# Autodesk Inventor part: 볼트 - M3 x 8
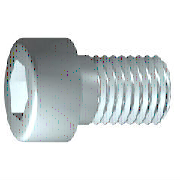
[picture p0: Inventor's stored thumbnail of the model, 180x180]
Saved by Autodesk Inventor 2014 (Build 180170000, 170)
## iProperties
IsCustomPart: 0
Created: 2012-02
Part Number: 볼트 - M3 x 8
Material: 스테인리스강
Description: 6각 소켓 머리 캡 나사
Document SubType Name: Modeling
Standard: ISO 4762
Designer: mduedu
Standard Revision: Fourth edition 2004-03-01
Standards Organization: ISO
Language: ko-KR
Size Designation: M3 x 8
Categories: <MemberInstance><Categories><Category DisplayName="조임쇠" InternalName="e4da775c-781d-43d5-af7c-5136215cf5a6" Mnemonic="FSTN"><Category DisplayName="볼트" InternalN
Density: 8.08 g/cm^3
Appearance: 반광택
Mass: 0.95587 g
Surface Area: 1.83001 cm^2
Volume: 0.118301 cm^3
Author: mduedu
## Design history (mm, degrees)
sketch "스케치1"
  geometry: L1 (-0.867, 0)-(8, 0); L2 (8, 0)-(8, 1.5); L3 (8, 1.5)-(1.25, 1.5); L4 (1.25, 1.5)-(0.943, 1.5); L5 (0.943, 1.5)-(0, 1.5); L6 (0, 1.5)-(0, 2.75); L7 (0, 2.75)-(-3, 2.75); L8 (-3, 2.75)-(-3, 1.443); L9 (-3, 1.443)-(-1.7, 1.443); L10 (-1.7, 1.443)-(-0.867, 0); L11 (-5.2, 0)-(10.2, 0) reference; L12 (0, -0.55)-(0, 3.3) reference; L13 (1.25, 1.5)-(0, 1.5)
  constraints: 22 end point, 6 parallel, 2 collinear, 2 perpendicular, 1 horizontal, 1 point on line
  dimensions: "d1" = 6.75 distance from line of L3.end L2 (= GEL); "d2" = 0.30683 distance of L4.end L3.end (computed from GAL); "d3" = 3 distance between parallel lines of L8 L6 (= KOH); "d4" = 1.3 distance of L8.end L9.end (= INTI); "d5" = 60 deg angle of L10 L1; "d6" = 3 diameter of L3 L1 (= GD); "d7" = 3 diameter of L5 L1 (= BDM); "d8" = 2.88675 diameter of L9 L1 (= 1.1547 x SW); "d9" = 5.5 diameter of L7 L1 (= KOD); "d26" = 8 distance between parallel lines of L12 L2 (= NLG)
revolve "본체" sketch "스케치1" stored, may be unused: angle "d10" = 90 deg
sketch "스케치2"
  geometry: L1 (0, -3.85)-(0, 3.85) reference; L2 (-3.85, 0)-(3.85, 0) reference; L3 (1.443, 0)-(0.722, -1.25); L4 (0.722, -1.25)-(-0.722, -1.25); L5 (-0.722, -1.25)-(-1.443, 0); L6 (-1.443, 0)-(-0.722, 1.25); L7 (-0.722, 1.25)-(0.722, 1.25); L8 (0.722, 1.25)-(1.443, 0); 2 further points
  constraints: 12 end point, 1 coincident, 1 horizontal alignment, 1 point on line, 12 other
extrude "슬롯" join sketch "스케치2" stored distance "d11" = 10; taper "d12" = 0 deg
workplane "Work Plane1"
fillet "Fillet2" dims "d30" = 0.1 (= R)
body "Solid1"
fillet "모깎기1" dims "d17" = 0.3 (= RR)
feature "스레드" dims "d13" = 6.75 (= GEL), "d14" = 0
chamfer "모따기1" distance "d15" = 0.30673 (= -0.5 x SPD + 0.5 x GD); stored, may be unused: second distance "d16" = 0.30673 (= GUL), angle "d27" = 45 deg
other parameters: "GD" = 3 [user parameter; used in 2 equation terms], "NLG" = 8 [user parameter; used in 1 equation term], "GEL" = 6.75 [user parameter; used in 2 equation terms], "KOD" = 5.5 [user parameter; used in 1 equation term], "KOH" = 3 [user parameter; used in 1 equation term], "INTI" = 1.3 [user parameter; used in 1 equation term], "GAL" = 0.30673 (= 0.61345 x PTC) [user parameter; used in 1 equation term], "GUL" = 0.30673 (= 0.61345 x PTC) [user parameter; used in 1 equation term], "BDM" = 3 (= NND) [user parameter; used in 1 equation term], "SW" = 2.5 [user parameter; used in 2 equation terms], "RR" = 0.3 [user parameter; used in 1 equation term], "SPD" = 2.38655 (= NND - 1.2269 x PTC) [user parameter; used in 1 equation term], "d19" = 0, "d28" = 0, "d29" = 0, "R" = 0.1 [user parameter; used in 1 equation term], "TOA" = 30 deg [user parameter], "GD1" = 2.38655 (= THREADDIA - 1.2269 x PTC) [user parameter], "THREADDIA" = 3 [user parameter; used in 1 equation term], "FAWI" = 45 deg [user parameter], "PTC" = 0.5 [user parameter; used in 5 equation terms], "NND" = 3 [user parameter; used in 2 equation terms], "E0" = 2.8875 (= 1.155 x SW) [user parameter]
